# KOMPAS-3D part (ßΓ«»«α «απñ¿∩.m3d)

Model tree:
1. Эскиз:1
2. Операция выдавливания:1
     Расстояние 1 = 5; Расстояние 2 = 1
3. Эскиз:2
4. Отверстие:1

Referenced files in C:\Program Files\ASCON\KOMPAS-3D V13 Home\Sys\: holelib.lfr
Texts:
  stalker61
  Сплав АЛ8  ГОСТ 1583-93
  Отверстие 01
  (вариант 1)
